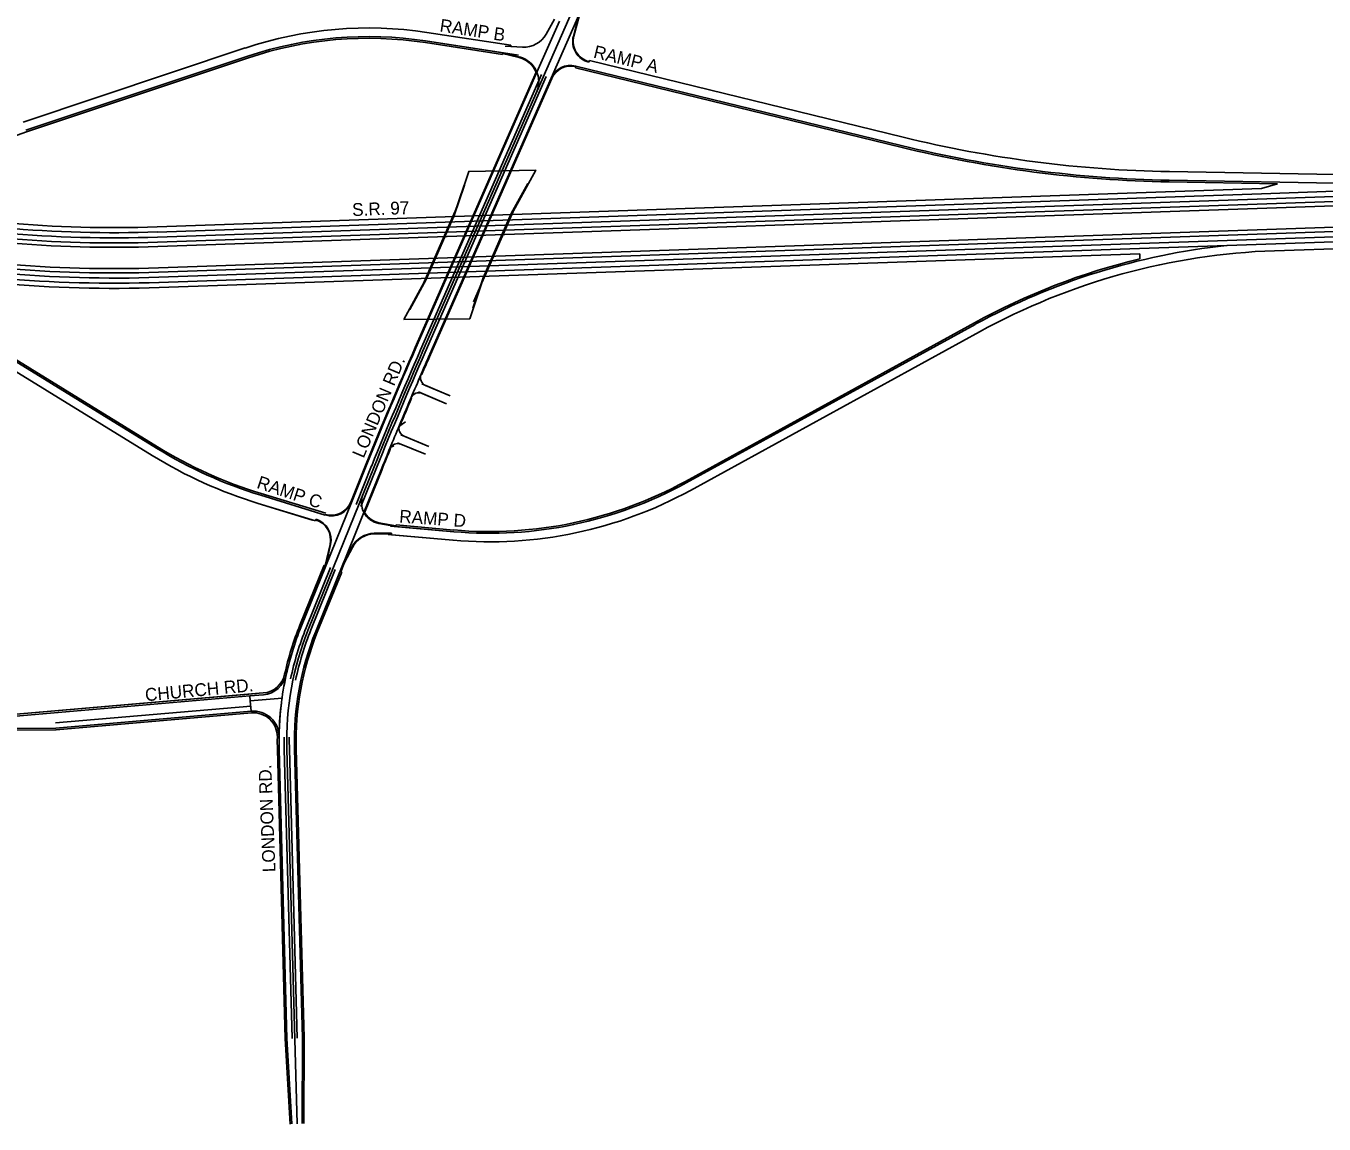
# Model space of a CAD drawing. Extents: x 2315515 to 2326910, y 758186 to 762794.
# Drawn here: x 2319969 to 2323003, y 758186 to 760752 of the extents above; entities that cross this region are included whole.
import ezdxf

# ---------------------------------------------------------------- set-up
doc = ezdxf.new("R2010")
doc.units = 0
for name, color, linetype in [('_CIVIL_CONSTRUCTION', 7, 'Continuous'), ('Bridge_Abutment', 7, 'Continuous'), ('Bridge_Bearing', 7, 'Continuous'), ('Bridge_Deck', 7, 'Continuous'), ('Clipping_Shape', 7, 'Continuous'), ('Default', 7, 'Continuous'), ('Draft_Corr_Design', 7, 'Continuous'), ('Draft_Corr_Range_Design', 7, 'Continuous'), ('E_Terrain_Exterior', 7, 'Continuous'), ('Pavement Marking Yellow', 7, 'Continuous'), ('Road_Curb_Face', 7, 'Continuous'), ('TL_Base Extension Sub', 7, 'Continuous'), ('TL_End Condition Ditch In', 7, 'Continuous'), ('TL_End Condition Ditch Out', 7, 'Continuous'), ('TL_Pavement Centerline', 7, 'Continuous'), ('TL_Pavement Centerline Sub', 7, 'Continuous')]:
    doc.layers.add(name, color=color, linetype=linetype)

msp = doc.modelspace()

# ---------------------------------------------------------------- linework, layer by layer
at = {"layer": '_CIVIL_CONSTRUCTION'}
for p, q in [((2320276.5, 760246.3), (2324006, 760375.3)), ((2320278.9, 760176.4), (2324008.4, 760305.3))]:
    msp.add_line(p, q, dxfattribs=at)
for radius in [2931, 3001]:
    msp.add_arc((2320175.2, 763175.6), radius, 264.9144, 271.9805, dxfattribs=at)
at = {"layer": 'Bridge_Abutment'}
for p, q in [((2321103.2, 760313.3), (2321141.6, 760383.5)), ((2320970, 760308.5), (2320994, 760379.5)), ((2320904.4, 760159.2), (2320970, 760308.5)), ((2321037.2, 760163.2), (2321103.2, 760313.3)), ((2320866, 760089.1), (2320904.4, 760159.2)), ((2321013.2, 760092.1), (2321037.2, 760163.2))]:
    msp.add_line(p, q, dxfattribs=at)
at = {"layer": 'Bridge_Bearing'}
for p, q in [((2321141.6, 760383.5), (2321103.2, 760313.3)), ((2320994, 760379.5), (2320970, 760308.5)), ((2320904.4, 760159.2), (2320970, 760308.5)), ((2321037.2, 760163.2), (2321103.2, 760313.3)), ((2320866, 760089.1), (2320904.4, 760159.2)), ((2321013.2, 760092.1), (2321037.2, 760163.2))]:
    msp.add_line(p, q, dxfattribs=at)
at = {"layer": 'Bridge_Deck'}
for p, q in [((2320891.3, 760134.3), (2320977.7, 760331.1)), ((2320946.3, 760259.5), (2320966.8, 760306.2)), ((2321014.9, 760107.4), (2321107.7, 760318.6)), ((2321083.8, 760264.2), (2321104.3, 760311)), ((2320903.4, 760161.9), (2320924, 760208.7)), ((2321041, 760166.7), (2321061.5, 760213.4))]:
    msp.add_line(p, q, dxfattribs=at)
at = {"layer": 'Clipping_Shape'}
for p, q in [((2320969.1, 760308.8), (2320993.1, 760379.8)), ((2320903.6, 760159.7), (2320969.1, 760308.8)), ((2320865.1, 760089.5), (2320903.6, 760159.7))]:
    msp.add_line(p, q, dxfattribs=at)
msp.add_lwpolyline([(2320852.2, 760066.2), (2320904.3, 760161.4), (2320968.5, 760307.7), (2321003.8, 760411.9), (2321160.3, 760415.2), (2321103.4, 760311.5), (2321039.2, 760165.2), (2321006.2, 760067.6)], close=True, dxfattribs=at)
at = {"layer": 'Default'}
for p, q in [((2320896.6, 759992.2), (2321353.4, 761032.3)), ((2320896.6, 759992.2), (2321353.4, 761032.3)), ((2320896.6, 759992.2), (2321353.4, 761032.3)), ((2320840.7, 759815.8), (2320856, 759826.5)), ((2320820.4, 759766.7), (2320828.3, 759770.7)), ((2320629.4, 759343.1), (2320782.4, 759721.3)), ((2320629.4, 759343.1), (2320782.4, 759721.3)), ((2320629.4, 759343.1), (2320782.4, 759721.3)), ((2320602.3, 758186.1), (2320578.6, 759061.6)), ((2320602.3, 758186.1), (2320578.6, 759061.6)), ((2320602.3, 758186.1), (2320578.6, 759061.6))]:
    msp.add_line(p, q, dxfattribs=at)
for centre, radius, start, end in [((2330052.7, 755971.5), 10000, 156.2923, 157.9768), ((2330052.7, 755971.5), 10000, 156.2923, 157.9768), ((2330052.7, 755971.5), 10000, 156.2923, 157.9768), ((2321278.3, 759080.6), 700, 157.9768, 181.5499), ((2321278.3, 759080.6), 700, 157.9768, 181.5499), ((2321278.3, 759080.6), 700, 157.9768, 181.5499)]:
    msp.add_arc(centre, radius, start, end, dxfattribs=at)
at = {"layer": 'Draft_Corr_Design'}
for p, q in [((2320276.8, 760236.3), (2324006.3, 760365.3)), ((2320278.5, 760186.3), (2324008.1, 760315.3))]:
    msp.add_line(p, q, dxfattribs=at)
for radius in [2941, 2991]:
    msp.add_arc((2320175.2, 763175.6), radius, 264.9144, 271.9805, dxfattribs=at)
at = {"layer": 'Draft_Corr_Range_Design'}
for p, q in [((2320276.1, 760258.3), (2324005.6, 760387.3)), ((2320279.3, 760164.4), (2324008.8, 760293.3)), ((2320037.8, 759122.9), (2320494.2, 759162.3))]:
    msp.add_line(p, q, dxfattribs=at)
for radius in [2919, 3013]:
    msp.add_arc((2320175.2, 763175.6), radius, 264.9144, 271.9805, dxfattribs=at)
at = {"layer": 'E_Terrain_Exterior'}
for p, q in [((2321248.3, 760728.3), (2321261, 760777.3)), ((2321184.8, 760732.9), (2321204.5, 760767.9)), ((2320902.9, 760716.9), (2321120.3, 760683.6)), ((2320902.9, 760716.9), (2321083.3, 760689.3)), ((2321083.3, 760689.3), (2321122.2, 760679.3)), ((2321083.3, 760689.3), (2321122.2, 760679.3)), ((2321089.2, 760704.6), (2321129.4, 760702.5)), ((2319968.8, 760508), (2320487.5, 760681.4)), ((2319968.8, 760508), (2320487.5, 760681.4)), ((2321253.9, 760658.1), (2322014.4, 760472.4)), ((2321253.9, 760658.1), (2322014.4, 760472.4)), ((2320880.1, 759999.4), (2321163, 760643.5)), ((2320880.1, 759999.4), (2321163, 760643.5)), ((2320913.1, 759984.9), (2321196.2, 760629.7)), ((2320913.1, 759984.9), (2321196.2, 760629.7)), ((2322641, 760391.4), (2323391.1, 760378)), ((2322641, 760391.4), (2323391.1, 760378)), ((2321512.1, 759684), (2322187.7, 760054.5)), ((2321512.1, 759684), (2322187.7, 760054.5)), ((2319848.5, 760026.7), (2320274.1, 759765)), ((2320886.3, 759897), (2320952.1, 759868.7)), ((2320894.2, 759915.3), (2320960, 759887.1)), ((2320903, 759911.6), (2320960, 759887.1)), ((2320895.2, 759893.2), (2320952.1, 759868.7)), ((2320837.1, 759777.7), (2320902.4, 759750.7)), ((2320844.8, 759796.2), (2320910.1, 759769.1)), ((2320845.2, 759774.4), (2320902.4, 759750.7)), ((2320852.8, 759792.8), (2320910.1, 759769.1)), ((2320729.3, 759638), (2320765.7, 759728)), ((2320729.3, 759638), (2320765.7, 759728)), ((2320758.7, 759614.8), (2320799.1, 759714.5)), ((2320758.7, 759614.8), (2320799.1, 759714.5)), ((2320517.6, 759655.1), (2320668.3, 759608.9)), ((2320782.8, 759566.1), (2320823, 759566.6)), ((2320833, 759581.8), (2320793.5, 759589.3)), ((2320833, 759581.8), (2320793.5, 759589.3)), ((2320820.8, 759582.8), (2320968.7, 759569.9)), ((2320833, 759581.8), (2320968.7, 759569.9)), ((2320669.6, 759490.4), (2320680.9, 759539.8)), ((2320711.7, 759498.5), (2320730.4, 759534)), ((2320612.7, 759349.8), (2320680.2, 759516.6)), ((2320646.1, 759336.3), (2320712.8, 759501.1)), ((2320612.7, 759349.8), (2320669.6, 759490.4)), ((2320646.1, 759336.3), (2320711.7, 759498.5)), ((2319886.9, 759134), (2320492.1, 759186.2)), ((2320492.1, 759186.2), (2320523.9, 759189)), ((2320492.1, 759186.2), (2320523.9, 759189)), ((2320492.1, 759186.2), (2320493.2, 759174.3)), ((2320495.2, 759150.3), (2320493.2, 759174.3)), ((2320038.8, 759111), (2320495.2, 759150.3)), ((2320038.8, 759111), (2320495.2, 759150.3)), ((2319889, 759110.1), (2320038.8, 759111)), ((2320578.9, 758385.5), (2320560.6, 759061.2)), ((2320578.9, 758385.5), (2320560.6, 759061.2)), ((2320614.8, 758386.5), (2320596.6, 759062.1)), ((2320614.8, 758386.5), (2320596.6, 759062.1)), ((2320590.3, 758185.7), (2320578.9, 758385.5)), ((2320614.3, 758186.4), (2320614.8, 758386.5))]:
    msp.add_line(p, q, dxfattribs=at)
for centre, radius, start, end in [((2320768.6, 759840.1), 887, 81.2923, 108.4803), ((2320768.6, 759840.1), 887, 81.2923, 108.4803), ((2321132.5, 760762.4), 60, 267.0029, 330.5817), ((2321296.6, 760715.6), 50, 165.3826, 256.2777), ((2321107.3, 760621.2), 60, 336.2923, 75.5817), ((2321107.3, 760621.2), 60, 21.8653, 75.5817), ((2321242, 760609.6), 50, 76.2777, 156.2923), ((2322691.8, 763246.9), 2856, 256.2777, 268.9805), ((2322691.8, 763246.9), 2856, 256.2777, 268.9805), ((2322940.8, 758681.5), 1566, 96.0766, 118.7415), ((2322940.8, 758681.5), 1566, 96.0766, 118.7415), ((2330052.7, 755971.5), 10018, 156.2923, 157.9768), ((2330052.7, 755971.5), 10018, 156.2923, 157.9768), ((2330052.7, 755971.5), 9982, 156.2923, 156.67031), ((2330052.7, 755971.5), 9982, 156.2923, 156.58701), ((2320910.9, 759929.9), 20, 156.587, 246.7596), ((2330052.7, 755971.5), 9982, 156.82209, 157.38068), ((2330052.7, 755971.5), 9982, 156.93209, 157.32833), ((2320887.3, 759874.8), 20, 66.7596, 156.9321), ((2320860.5, 759811.3), 20, 157.3283, 247.5009), ((2330052.7, 755971.5), 9982, 157.60715, 157.9768), ((2320837.5, 759755.9), 20, 67.5009, 157.6734), ((2320826.1, 760662.9), 1054, 238.4184, 252.9768), ((2330052.7, 755971.5), 9982, 157.67342, 157.9768), ((2321052.4, 760522.2), 956, 264.9768, 298.7415), ((2321052.4, 760522.2), 956, 264.9768, 298.7415), ((2320802.8, 759638.4), 50, 157.9768, 259.2662), ((2320682.9, 759656.8), 50, 252.9768, 337.9768), ((2320632.2, 759551), 50, 347.0671, 72.9768), ((2320802.8, 759638.4), 50, 208.185, 259.2662), ((2320783.5, 759506.1), 60, 90.6874, 152.2662), ((2321278.3, 759080.6), 718, 157.9768, 168.1459), ((2321278.3, 759080.6), 718, 157.9768, 168.1459), ((2321278.3, 759080.6), 682, 157.9768, 181.5499), ((2321278.3, 759080.6), 682, 157.9768, 181.5499), ((2320518.7, 759248.7), 60, 274.9294, 347.5179), ((2320518.7, 759248.7), 60, 274.9294, 347.5179), ((2321278.3, 759080.6), 718, 172.8394, 181.5499), ((2320500.4, 759090.6), 60, 359.264, 94.9294), ((2321278.3, 759080.6), 718, 179.264, 181.5499)]:
    msp.add_arc(centre, radius, start, end, dxfattribs=at)
at = {"layer": 'Pavement Marking Yellow'}
for p, q in [((2320891.1, 759994.6), (2321174, 760638.7)), ((2320902.1, 759989.8), (2321185, 760633.9)), ((2320740.4, 759633.5), (2320776.8, 759723.5)), ((2320751.5, 759628.9), (2320787.9, 759719)), ((2320623.8, 759345.3), (2320680.7, 759485.9)), ((2320635, 759340.8), (2320691.8, 759481.4)), ((2320590.9, 758385.8), (2320572.6, 759061.5)), ((2320602.9, 758386.2), (2320584.6, 759061.8))]:
    msp.add_line(p, q, dxfattribs=at)
for centre, radius, start, end in [((2330052.7, 755971.5), 10006, 156.2923, 157.9768), ((2330052.7, 755971.5), 9994, 156.2923, 157.9768), ((2321278.3, 759080.6), 706, 157.9768, 168.1459), ((2321278.3, 759080.6), 694, 157.9768, 168.1459), ((2321278.3, 759080.6), 706, 179.264, 181.5499), ((2321278.3, 759080.6), 694, 179.264, 181.5499)]:
    msp.add_arc(centre, radius, start, end, dxfattribs=at)
at = {"layer": 'Road_Curb_Face'}
for p, q in [((2321249.7, 760727.9), (2321262.5, 760776.9)), ((2321249.7, 760727.9), (2321262.5, 760776.8)), ((2321082.9, 760687.8), (2321121.9, 760677.8)), ((2321083.1, 760687.8), (2321121.9, 760677.8)), ((2320878.8, 760000), (2321161.6, 760644.1)), ((2320878.8, 760000), (2321161.4, 760643.5)), ((2320914.5, 759984.3), (2321197.6, 760629.1)), ((2320727.9, 759638.6), (2320764.3, 759728.6)), ((2320727.9, 759638.6), (2320764.3, 759728.6)), ((2320760.1, 759614.2), (2320800.5, 759714)), ((2320760.4, 759614.9), (2320800.5, 759714)), ((2320782.8, 759564.6), (2320823, 759565.1)), ((2320833.3, 759583.3), (2320793.8, 759590.7)), ((2320833.3, 759583.3), (2320793.8, 759590.7)), ((2320668.1, 759490.8), (2320679.5, 759540.1)), ((2320668.2, 759491), (2320679.5, 759540.1)), ((2320713, 759497.8), (2320731.7, 759533.3)), ((2320704.4, 759476.4), (2320713, 759497.8))]:
    msp.add_line(p, q, dxfattribs=at)
for centre, radius, start, end in [((2321296.6, 760715.6), 48.5, 165.3826, 256.2777), ((2321296.6, 760715.6), 48.5, 165.3826, 256.2777), ((2321107.3, 760621.2), 58.5, 23.8009, 75.5817), ((2321107.3, 760621.2), 58.5, 22.4792, 75.5817), ((2321242, 760609.6), 48.5, 76.2777, 156.2923), ((2330052.7, 755971.5), 10019.5, 156.2923, 157.9768), ((2330052.7, 755971.5), 10019.5, 156.2923, 157.9768), ((2330052.7, 755971.5), 9980.5, 156.2923, 156.58701), ((2330052.7, 755971.5), 9980.5, 156.93209, 157.33984), ((2330052.7, 755971.5), 9980.5, 157.66192, 157.9768), ((2330052.7, 755971.5), 9980.5, 157.66192, 157.9768), ((2320682.9, 759656.8), 48.5, 252.9768, 337.9768), ((2320632.2, 759551), 48.5, 347.0671, 72.9768), ((2320632.2, 759551), 48.5, 347.0671, 72.9768), ((2320802.8, 759638.4), 48.5, 209.0103, 259.2662), ((2320802.8, 759638.4), 48.5, 212.6887, 259.2662), ((2320783.5, 759506.1), 58.5, 90.6874, 152.2662)]:
    msp.add_arc(centre, radius, start, end, dxfattribs=at)
at = {"layer": 'TL_Base Extension Sub'}
for p, q in [((2320275.6, 760270.3), (2322857, 760359.6)), ((2320279.7, 760152.4), (2322571.6, 760231.6))]:
    msp.add_line(p, q, dxfattribs=at)
for radius in [2907, 3025]:
    msp.add_arc((2320175.2, 763175.6), radius, 264.9144, 271.9805, dxfattribs=at)
at = {"layer": 'TL_End Condition Ditch In'}
for p, q in [((2321196.2, 760629.7), (2321261, 760777.3)), ((2321163, 760643.5), (2321215.5, 760763.1)), ((2322857, 760359.6), (2323696.6, 760388.6)), ((2322571.6, 760231.6), (2323686.3, 760270.2)), ((2320669.6, 759490.4), (2320729.3, 759638)), ((2320703, 759476.9), (2320758.7, 759614.8))]:
    msp.add_line(p, q, dxfattribs=at)
for centre, radius, start, end in [((2330052.7, 755971.5), 9982, 156.58701, 156.93209), ((2330052.7, 755971.5), 9982, 157.33984, 157.66192), ((2321278.3, 759080.6), 718, 167.5179, 179.264)]:
    msp.add_arc(centre, radius, start, end, dxfattribs=at)
at = {"layer": 'TL_End Condition Ditch Out'}
msp.add_line((2320493.2, 759174.3), (2320567.3, 759180.7), dxfattribs=at)
at = {"layer": 'TL_Pavement Centerline'}
for p, q in [((2320905.9, 760736.7), (2321102.1, 760706.6)), ((2320905.9, 760736.7), (2321102.1, 760706.6)), ((2319962.4, 760527), (2320481.1, 760700.4)), ((2319962.4, 760527), (2320481.1, 760700.4)), ((2320902.3, 760713), (2321082.7, 760685.3)), ((2321083.3, 760689.3), (2321082.7, 760685.3)), ((2321101.5, 760702.7), (2321102.1, 760706.6)), ((2319970, 760504.2), (2320488.7, 760677.6)), ((2321253.9, 760658.1), (2321252.9, 760654.3)), ((2321252.9, 760654.3), (2322013.4, 760468.6)), ((2321284.8, 760667.1), (2321285.7, 760671)), ((2321285.7, 760671), (2322019.1, 760491.9)), ((2322641.4, 760411.4), (2323583.4, 760394.6)), ((2322641, 760387.4), (2322893.8, 760382.9)), ((2322856.6, 760371.6), (2322893.8, 760382.9)), ((2322887.3, 760226.5), (2323387, 760243.8)), ((2322887.3, 760226.5), (2323387, 760243.8)), ((2322572, 760219.6), (2322572.4, 760207.6)), ((2321510.1, 759687.5), (2322185.8, 760058)), ((2319850.6, 760030.1), (2320276.2, 759768.4)), ((2321521.7, 759666.4), (2322197.4, 760037)), ((2321521.7, 759666.4), (2322197.4, 760037)), ((2319838, 760009.6), (2320263.7, 759748)), ((2319838, 760009.6), (2320263.7, 759748)), ((2320518.7, 759658.9), (2320669.5, 759612.8)), ((2320511.7, 759636), (2320638.4, 759597.2)), ((2320511.7, 759636), (2320645.7, 759595)), ((2320646.8, 759598.8), (2320645.7, 759595)), ((2320815.4, 759563.2), (2320966.9, 759549.9)), ((2320823.2, 759566.6), (2320822.8, 759562.6)), ((2320822.8, 759562.6), (2320966.9, 759549.9)), ((2320833.4, 759581.7), (2320833.7, 759585.7)), ((2320833.7, 759585.7), (2320969, 759573.8)), ((2320609, 759351.3), (2320665.9, 759491.9)), ((2320649.8, 759334.8), (2320706.7, 759475.4)), ((2320669.6, 759490.4), (2320665.9, 759491.9)), ((2320703, 759476.9), (2320706.7, 759475.4)), ((2319886.6, 759138), (2320523.5, 759192.9)), ((2319886.6, 759138), (2320507.4, 759191.5)), ((2320039, 759107), (2320495.6, 759146.4)), ((2320039.2, 759107), (2320495.6, 759146.4)), ((2319888.5, 759106.1), (2320039, 759107)), ((2319889, 759106.1), (2320038.9, 759107)), ((2320574.9, 758385.4), (2320556.6, 759061)), ((2320574.9, 758385.3), (2320556.6, 759061)), ((2320618.8, 758386.6), (2320600.6, 759062.2)), ((2320586.3, 758185.5), (2320574.9, 758385.3)), ((2320586.3, 758185.5), (2320574.9, 758385.3)), ((2320618.3, 758186.4), (2320618.8, 758386.5)), ((2320618.3, 758186.4), (2320618.8, 758386.5))]:
    msp.add_line(p, q, dxfattribs=at)
for centre, radius, start, end in [((2320768.6, 759840.1), 907, 81.2923, 108.4803), ((2320768.6, 759840.1), 907, 81.2923, 108.4803), ((2320768.6, 759840.1), 883, 81.2923, 108.4803), ((2319073, 763188.3), 2830, 273.5389, 288.4803), ((2322691.8, 763246.9), 2836, 256.2777, 268.9805), ((2322691.8, 763246.9), 2860, 256.2777, 268.9805), ((2322940.8, 758681.5), 1570, 103.5684, 118.7415), ((2322940.8, 758681.5), 1546, 91.9805, 118.7415), ((2322940.8, 758681.5), 1546, 91.9805, 118.7415), ((2320826.1, 760662.9), 1074, 238.4184, 252.9768), ((2320826.1, 760662.9), 1074, 238.4184, 252.9768), ((2320826.1, 760662.9), 1050, 238.4184, 252.9768), ((2321052.4, 760522.2), 952, 264.9768, 298.7415), ((2321052.4, 760522.2), 976, 264.9768, 298.7415), ((2321052.4, 760522.2), 976, 264.9768, 298.7415), ((2321278.3, 759080.6), 722, 157.9768, 167.5179), ((2321278.3, 759080.6), 678, 157.9768, 181.5499), ((2320518.7, 759248.7), 56, 274.9294, 347.5179), ((2320518.7, 759248.7), 56, 274.9294, 347.5179), ((2320500.4, 759090.6), 56, 359.264, 94.9294), ((2321278.3, 759080.6), 722, 179.264, 181.5499), ((2321278.3, 759080.6), 722, 179.264, 181.5499)]:
    msp.add_arc(centre, radius, start, end, dxfattribs=at)
at = {"layer": 'TL_Pavement Centerline Sub'}
for p, q in [((2320275.2, 760282.3), (2322856.6, 760371.6)), ((2320280.1, 760140.4), (2322572, 760219.6))]:
    msp.add_line(p, q, dxfattribs=at)
for radius in [2895, 3037]:
    msp.add_arc((2320175.2, 763175.6), radius, 264.9144, 271.9805, dxfattribs=at)

# ---------------------------------------------------------------- texts
at = {"layer": 'Default'}
for s, rotation, p in [('RAMP B', 351.3639, (2320934.5, 760739)), ('RAMP A', 346.2856, (2321293.4, 760678.2)), ('S.R. 97', 2.1074, (2320731.7, 760307.5)), ('LONDON RD.', 67.0887, (2320757.9, 759740)), ('RAMP C', 341.6007, (2320506.3, 759672.7)), ('RAMP D', 355.8776, (2320840.6, 759591.4)), ('CHURCH RD.', 5.3529, (2320248.5, 759173.5)), ('LONDON RD.', 92.2882, (2320552.1, 758774.7))]:
    msp.add_text(s, height=30, rotation=rotation, dxfattribs=at).set_placement(p)

doc.saveas('drawing.dxf')
